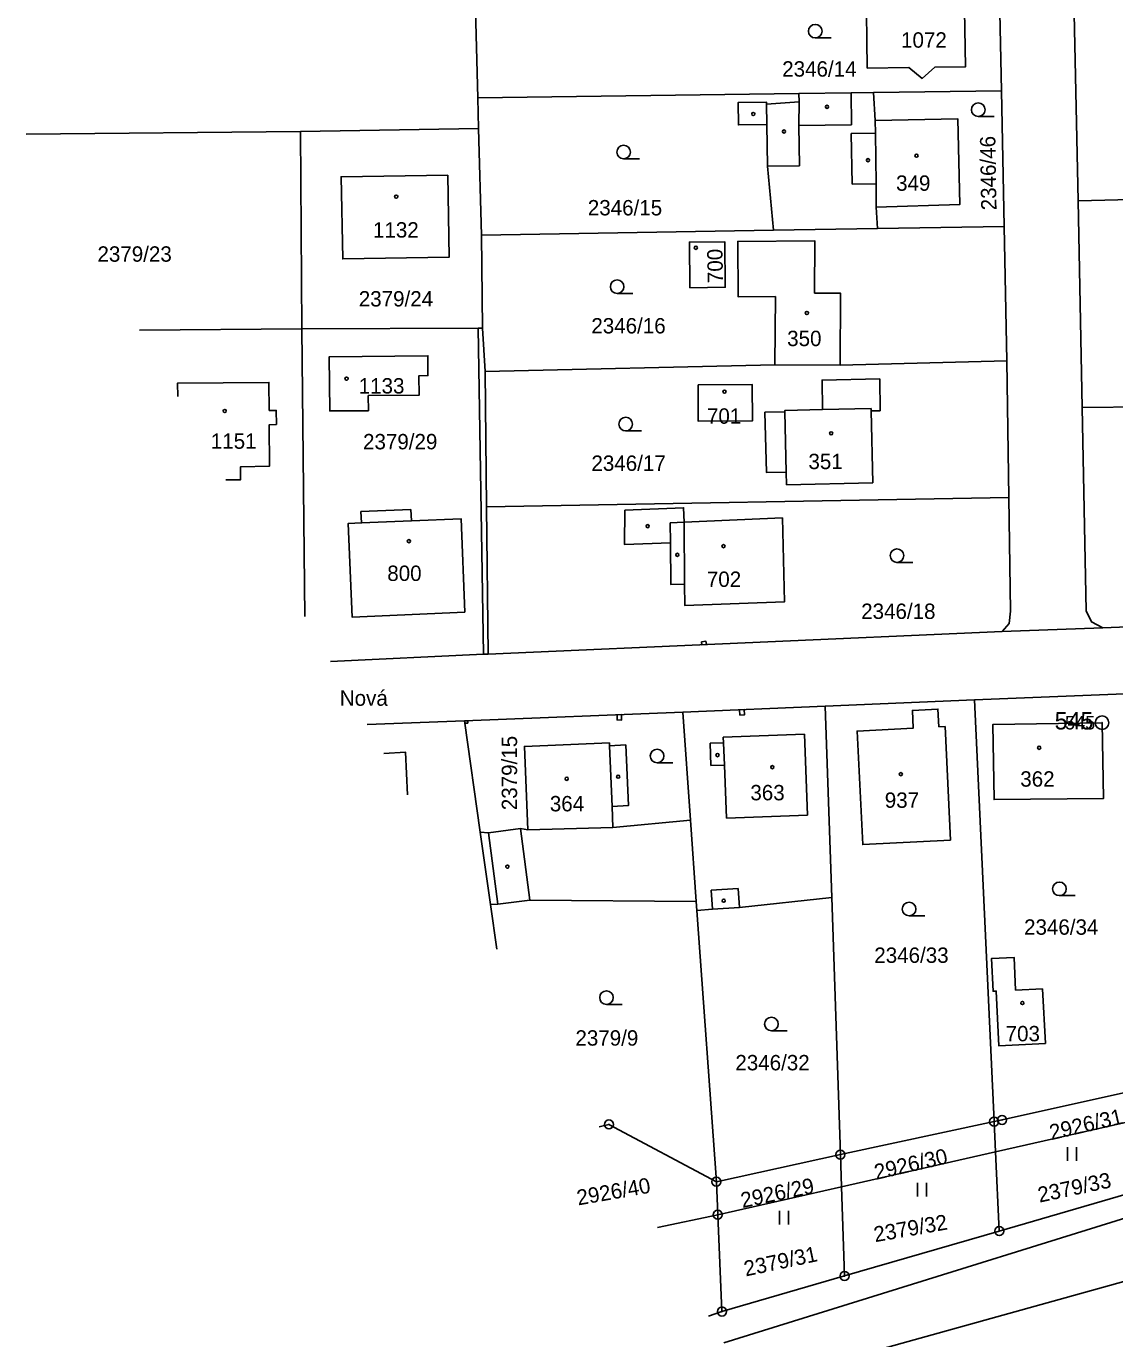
# Model space of a CAD drawing. Extents: x -758836 to -757729, y -1175316 to -1174366.
# Drawn here: x -758829.6 to -758709.3, y -1175013.2 to -1174868.1 of the extents above; entities that cross this region are included whole.
import ezdxf

# ---------------------------------------------------------------- set-up
doc = ezdxf.new("R2010")
doc.units = 0
for name, color, linetype in [('Hranice parcel', 7, 'Continuous'), ('Parcelní čísla', 7, 'Continuous'), ('Pop  PČ popisy', 7, 'Continuous'), ('Vnitřní kresba', 7, 'Continuous'), ('Věcná břemena k části', 7, 'Continuous'), ('Značky bodu BP', 7, 'Continuous'), ('Značky budov', 7, 'Continuous'), ('Značky kultur', 7, 'Continuous')]:
    doc.layers.add(name, color=color, linetype=linetype)

msp = doc.modelspace()

# ---------------------------------------------------------------- linework, layer by layer
at = {"layer": 'Hranice parcel'}
for p, q in [((-758780.07, -1174860.85), (-758779.67, -1174875.98)), ((-758721.79, -1174875.22), (-758722.01, -1174864.11)), ((-758713.75, -1174866.68), (-758713.31, -1174887.37)), ((-758779.67, -1174875.98), (-758744.17, -1174875.51)), ((-758735.94, -1174875.41), (-758721.79, -1174875.22)), ((-758721.79, -1174875.22), (-758721.49, -1174890.19)), ((-758779.67, -1174875.98), (-758779.58, -1174879.39)), ((-758799.28, -1174879.69), (-758779.58, -1174879.39)), ((-758799.14, -1174901.53), (-758799.28, -1174879.69)), ((-758779.58, -1174879.39), (-758779.27, -1174891.16)), ((-758713.31, -1174887.37), (-758668.75, -1174886.35)), ((-758713.31, -1174887.37), (-758712.85, -1174910.23)), ((-758721.49, -1174890.19), (-758735.49, -1174890.42)), ((-758721.19, -1174905.07), (-758721.49, -1174890.19)), ((-758779.27, -1174891.16), (-758746.99, -1174890.62)), ((-758779.27, -1174891.16), (-758779.15, -1174901.44)), ((-758746.99, -1174890.62), (-758735.49, -1174890.42)), ((-758817.08, -1174901.67), (-758799.14, -1174901.53)), ((-758798.81, -1174933.31), (-758799.14, -1174901.53)), ((-758779.15, -1174901.44), (-758778.87, -1174906.24)), ((-758778.87, -1174906.24), (-758746.84, -1174905.5)), ((-758778.87, -1174906.24), (-758778.71, -1174921.21)), ((-758746.84, -1174905.5), (-758739.62, -1174905.55)), ((-758739.62, -1174905.55), (-758721.19, -1174905.07)), ((-758720.97, -1174920.18), (-758721.19, -1174905.07)), ((-758712.85, -1174910.23), (-758694.87, -1174909.97)), ((-758778.71, -1174921.21), (-758720.97, -1174920.18)), ((-758778.71, -1174921.21), (-758778.54, -1174937.47)), ((-758710.56, -1174934.59), (-758670.93, -1174932.75)), ((-758778.54, -1174937.47), (-758721.71, -1174934.99)), ((-758710.56, -1174934.59), (-758721.71, -1174934.99)), ((-758724.75, -1174942.54), (-758741.26, -1174943.23)), ((-758707.25, -1174941.82), (-758724.75, -1174942.54)), ((-758722.59, -1174989.16), (-758724.75, -1174942.54)), ((-758781.15, -1174944.87), (-758757.02, -1174943.88)), ((-758741.26, -1174943.23), (-758757.02, -1174943.88)), ((-758757.02, -1174943.88), (-758756.16, -1174955.85)), ((-758740.54, -1174964.37), (-758741.26, -1174943.23)), ((-758791.91, -1174945.27), (-758781.15, -1174944.87)), ((-758779.41, -1174957.17), (-758781.15, -1174944.87)), ((-758756.16, -1174955.85), (-758755.52, -1174964.83)), ((-758779.41, -1174957.17), (-758778.28, -1174965.17)), ((-758777.58, -1174970.08), (-758778.28, -1174965.17)), ((-758755.52, -1174964.83), (-758755.45, -1174965.82)), ((-758739.58, -1174992.81), (-758740.54, -1174964.37)), ((-758755.45, -1174965.82), (-758753.3, -1174995.8)), ((-758705.17, -1174988.61), (-758722.43, -1174992.51)), ((-758739.58, -1174992.81), (-758722.59, -1174989.16)), ((-758722.43, -1174992.51), (-758722.59, -1174989.16)), ((-758753.3, -1174995.8), (-758739.58, -1174992.81)), ((-758739.46, -1174996.37), (-758739.58, -1174992.81)), ((-758722.43, -1174992.51), (-758739.46, -1174996.37)), ((-758722.03, -1175001.26), (-758722.43, -1174992.51)), ((-758753.3, -1174995.8), (-758753.14, -1174999.46)), ((-758704.83, -1174996.27), (-758722.03, -1175001.26)), ((-758739.46, -1174996.37), (-758753.14, -1174999.46)), ((-758739.13, -1175006.22), (-758739.46, -1174996.37)), ((-758753.14, -1174999.46), (-758759.8, -1175000.88)), ((-758753.14, -1174999.46), (-758752.68, -1175010.15)), ((-758722.03, -1175001.26), (-758739.13, -1175006.22)), ((-758739.13, -1175006.22), (-758752.68, -1175010.15)), ((-758752.68, -1175010.15), (-758754.17, -1175010.65))]:
    msp.add_line(p, q, dxfattribs=at)
for points in [[(-758722.01, -1174864.11), (-758725.89, -1174864.14), (-758725.75, -1174872.55), (-758729.16, -1174872.6), (-758730.53, -1174873.84), (-758732.01, -1174872.64), (-758736.61, -1174872.7), (-758736.74, -1174863.47), (-758728.55, -1174863.36), (-758728.6, -1174860.45), (-758722.09, -1174860.37)], [(-758749.71, -1175018.36), (-758683.75, -1175000), (-758648.73, -1174990.25), (-758595.39, -1174971.76), (-758559.83, -1174954.39), (-758554.18, -1174950.69), (-758542.58, -1174943.09), (-758500.14, -1174908.44), (-758460.25, -1174869.94), (-758457.56, -1174867.46)], [(-758744.17, -1174875.51), (-758744.16, -1174876.44), (-758747.74, -1174876.67), (-758747.75, -1174876.47), (-758750.9, -1174876.51), (-758750.86, -1174878.98), (-758747.71, -1174878.94), (-758747.66, -1174883.53), (-758746.99, -1174890.62)], [(-758735.94, -1174875.41), (-758738.41, -1174875.44), (-758744.17, -1174875.51)], [(-758735.49, -1174890.42), (-758735.62, -1174888.06), (-758726.4, -1174887.78), (-758726.61, -1174878.29), (-758735.74, -1174878.49), (-758735.94, -1174875.41)], [(-758829.59, -1174880), (-758799.28, -1174879.69)], [(-758782.99, -1174884.52), (-758782.84, -1174893.61), (-758794.6, -1174893.79), (-758794.78, -1174884.71), (-758782.99, -1174884.52)], [(-758739.62, -1174905.55), (-758739.57, -1174897.59), (-758742.44, -1174897.57), (-758742.42, -1174891.78), (-758750.93, -1174891.86), (-758750.9, -1174897.97), (-758746.77, -1174897.95), (-758746.84, -1174905.5)], [(-758756.22, -1174896.98), (-758752.32, -1174896.92), (-758752.38, -1174891.89), (-758756.27, -1174891.93), (-758756.22, -1174896.98)], [(-758799.14, -1174901.53), (-758779.65, -1174901.44), (-758779.15, -1174901.44)], [(-758791.78, -1174908.9), (-758791.77, -1174910.58), (-758796.04, -1174910.6), (-758796.09, -1174904.6), (-758785.18, -1174904.49), (-758785.18, -1174906.69), (-758786.18, -1174906.7), (-758786.16, -1174908.87), (-758791.78, -1174908.9)], [(-758812.84, -1174909.01), (-758812.86, -1174907.52), (-758802.77, -1174907.44), (-758802.74, -1174910.55)], [(-758755.31, -1174907.72), (-758755.31, -1174911.73), (-758749.31, -1174911.7), (-758749.33, -1174907.69), (-758755.31, -1174907.72)], [(-758745.54, -1174918.76), (-758736.01, -1174918.54), (-758736.19, -1174910.59), (-758735.2, -1174910.58), (-758735.24, -1174907.05), (-758741.62, -1174907.18), (-758741.57, -1174910.45), (-758745.73, -1174910.55), (-758745.73, -1174910.7), (-758747.93, -1174910.75), (-758747.76, -1174917.4), (-758745.57, -1174917.35), (-758745.54, -1174918.76)], [(-758802.74, -1174910.55), (-758801.95, -1174910.53), (-758801.94, -1174912.09), (-758802.73, -1174912.13), (-758802.69, -1174916.69), (-758805.91, -1174916.79), (-758805.9, -1174918.2), (-758807.53, -1174918.22)], [(-758712.85, -1174910.23), (-758712.4, -1174932.68), (-758711.84, -1174933.91), (-758710.56, -1174934.59)], [(-758721.71, -1174934.99), (-758720.92, -1174934.1), (-758720.79, -1174932.73), (-758720.97, -1174920.18)], [(-758787.06, -1174921.48), (-758792.59, -1174921.72), (-758792.53, -1174922.98), (-758794.02, -1174923.04), (-758793.57, -1174933.38), (-758781.11, -1174932.84), (-758781.52, -1174922.51), (-758787.01, -1174922.74), (-758787.06, -1174921.48)], [(-758745.97, -1174922.41), (-758756.85, -1174922.88), (-758756.92, -1174921.29), (-758763.41, -1174921.57), (-758763.46, -1174925.35), (-758758.38, -1174925.18), (-758758.35, -1174929.77), (-758756.81, -1174929.76), (-758756.79, -1174932.1), (-758745.78, -1174931.71), (-758745.97, -1174922.41)], [(-758778.54, -1174937.47), (-758779.04, -1174937.49), (-758795.94, -1174938.3)], [(-758728.01, -1174945.47), (-758728.7, -1174945.51), (-758728.8, -1174943.55), (-758731.63, -1174943.7), (-758731.53, -1174945.66), (-758737.74, -1174945.99), (-758737.11, -1174958.54), (-758727.42, -1174958.04), (-758728.01, -1174945.47)], [(-758710.66, -1174945.06), (-758722.74, -1174945.27), (-758722.59, -1174953.55), (-758710.51, -1174953.44), (-758710.66, -1174945.06)], [(-758787.44, -1174953.02), (-758787.66, -1174948.32), (-758790.07, -1174948.45)], [(-758756.16, -1174955.85), (-758764.74, -1174956.64), (-758764.83, -1174954.31), (-758763.03, -1174954.23), (-758763.31, -1174947.52), (-758765.11, -1174947.6), (-758765.12, -1174947.3), (-758774.52, -1174947.68), (-758774.14, -1174956.9), (-758774.94, -1174956.76), (-758778.49, -1174957.22), (-758779.41, -1174957.17)], [(-758778.28, -1174965.17), (-758777.47, -1174965.13), (-758773.92, -1174964.68), (-758755.52, -1174964.83)], [(-758755.45, -1174965.82), (-758753.72, -1174965.69), (-758750.73, -1174965.48), (-758740.54, -1174964.37)], [(-758716.93, -1174980.54), (-758717.26, -1174974.49), (-758720.21, -1174974.62), (-758720.38, -1174971), (-758722.88, -1174971.11), (-758722.71, -1174974.74), (-758722.36, -1174974.72), (-758722.08, -1174980.78), (-758716.93, -1174980.54)], [(-758722.59, -1174989.16), (-758721.71, -1174988.97), (-758705.32, -1174985.3)], [(-758766.24, -1174989.74), (-758765.18, -1174989.47), (-758753.3, -1174995.8)], [(-758752.46, -1175013.6), (-758691.55, -1174994.68)]]:
    msp.add_lwpolyline(points, dxfattribs=at)
at = {"layer": 'Vnitřní kresba'}
for p, q in [((-758738.41, -1174875.44), (-758738.36, -1174878.97)), ((-758747.71, -1174878.94), (-758747.74, -1174876.67)), ((-758744.17, -1174879.04), (-758744.16, -1174876.44)), ((-758735.74, -1174878.49), (-758735.72, -1174879.88)), ((-758738.36, -1174878.97), (-758744.17, -1174879.04)), ((-758744.17, -1174879.04), (-758744.12, -1174883.49)), ((-758735.72, -1174879.88), (-758738.4, -1174879.92)), ((-758738.4, -1174879.92), (-758738.28, -1174885.53)), ((-758735.72, -1174879.88), (-758735.65, -1174885.5)), ((-758744.12, -1174883.49), (-758747.66, -1174883.53)), ((-758738.28, -1174885.53), (-758735.65, -1174885.5)), ((-758735.65, -1174885.5), (-758735.62, -1174888.06)), ((-758736.2, -1174910.33), (-758741.57, -1174910.45)), ((-758736.19, -1174910.59), (-758736.2, -1174910.33)), ((-758745.73, -1174910.7), (-758745.57, -1174917.35)), ((-758792.53, -1174922.98), (-758787.01, -1174922.74)), ((-758756.85, -1174922.88), (-758758.39, -1174922.95)), ((-758758.39, -1174922.95), (-758758.38, -1174925.18)), ((-758756.85, -1174922.88), (-758756.81, -1174929.76)), ((-758752.53, -1174946.66), (-758743.57, -1174946.31)), ((-758752.5, -1174947.27), (-758752.53, -1174946.66)), ((-758743.57, -1174946.31), (-758743.22, -1174955.27)), ((-758765.11, -1174947.6), (-758764.83, -1174954.31)), ((-758754, -1174947.33), (-758752.5, -1174947.27)), ((-758753.91, -1174949.8), (-758754, -1174947.33)), ((-758752.5, -1174947.27), (-758752.41, -1174949.74)), ((-758752.41, -1174949.74), (-758753.91, -1174949.8)), ((-758752.18, -1174955.61), (-758752.41, -1174949.74)), ((-758743.22, -1174955.27), (-758752.18, -1174955.61)), ((-758774.94, -1174956.76), (-758773.92, -1174964.68)), ((-758764.74, -1174956.64), (-758774.14, -1174956.9)), ((-758777.47, -1174965.13), (-758778.49, -1174957.22)), ((-758750.87, -1174963.38), (-758753.86, -1174963.58)), ((-758753.86, -1174963.58), (-758753.72, -1174965.69)), ((-758750.73, -1174965.48), (-758750.87, -1174963.38))]:
    msp.add_line(p, q, dxfattribs=at)
at = {"layer": 'Věcná břemena k části'}
for points in [[(-758779.65, -1174901.44), (-758779.04, -1174937.49), (-758778.54, -1174937.47), (-758778.71, -1174921.21), (-758778.87, -1174906.24), (-758779.15, -1174901.44)], [(-758754.9, -1174936.44), (-758754.39, -1174936.42), (-758754.45, -1174936.06), (-758754.94, -1174936.13)], [(-758750.7, -1174944.24), (-758750.2, -1174944.2), (-758750.24, -1174943.6), (-758750.74, -1174943.62)], [(-758781.15, -1174944.87), (-758781.12, -1174945.1), (-758780.78, -1174945.1), (-758780.78, -1174944.85)], [(-758763.77, -1174944.16), (-758764.27, -1174944.18), (-758764.28, -1174944.75), (-758763.78, -1174944.77)]]:
    msp.add_lwpolyline(points, close=True, dxfattribs=at)
at = {"layer": 'Značky bodu BP'}
for centre, radius in [((-758710.66, -1174945.06), 0.75), ((-758710.66, -1174945.06), 0.03), ((-758765.18, -1174989.47), 0.5), ((-758722.59, -1174989.16), 0.5), ((-758721.71, -1174988.97), 0.5), ((-758721.71, -1174988.97), 0.0303), ((-758765.18, -1174989.47), 0.0303), ((-758722.59, -1174989.16), 0.0303), ((-758739.58, -1174992.81), 0.5), ((-758739.58, -1174992.81), 0.0303), ((-758753.3, -1174995.8), 0.5), ((-758753.3, -1174995.8), 0.0303), ((-758753.14, -1174999.46), 0.5), ((-758753.14, -1174999.46), 0.0303), ((-758722.03, -1175001.26), 0.5), ((-758722.03, -1175001.26), 0.0303), ((-758739.13, -1175006.22), 0.5), ((-758739.13, -1175006.22), 0.0303), ((-758752.68, -1175010.15), 0.5), ((-758752.68, -1175010.15), 0.0303)]:
    msp.add_circle(centre, radius, dxfattribs=at)
at = {"layer": 'Značky budov'}
for centre in [(-758741.06, -1174876.98), (-758749.22, -1174877.77), (-758745.82, -1174879.7), (-758736.53, -1174882.87), (-758731.17, -1174882.38), (-758788.69, -1174886.9), (-758755.57, -1174892.56), (-758743.29, -1174899.76), (-758794.18, -1174907.02), (-758752.4, -1174908.46), (-758807.65, -1174910.6), (-758740.61, -1174913.07), (-758760.89, -1174923.33), (-758787.29, -1174924.99), (-758757.61, -1174926.5), (-758752.51, -1174925.54), (-758717.61, -1174947.83), (-758753.17, -1174948.64), (-758747.11, -1174949.98), (-758769.84, -1174951.26), (-758764.15, -1174951.03), (-758732.9, -1174950.75), (-758776.4, -1174960.97), (-758752.49, -1174964.74), (-758719.47, -1174976.05)]:
    msp.add_circle(centre, 0.175, dxfattribs=at)
at = {"layer": 'Značky kultur'}
for p, q in [((-758742.37, -1174869.36), (-758740.62, -1174869.36)), ((-758724.35, -1174878.05), (-758722.6, -1174878.05)), ((-758763.55, -1174882.73), (-758761.8, -1174882.73)), ((-758764.27, -1174897.61), (-758762.52, -1174897.61)), ((-758763.32, -1174912.8), (-758761.57, -1174912.8)), ((-758733.33, -1174927.34), (-758731.58, -1174927.34)), ((-758759.85, -1174949.49), (-758758.1, -1174949.49)), ((-758715.37, -1174964.18), (-758713.62, -1174964.18)), ((-758731.99, -1174966.41), (-758730.24, -1174966.41)), ((-758765.45, -1174976.2), (-758763.7, -1174976.2)), ((-758747.21, -1174979.12), (-758745.46, -1174979.12)), ((-758714.47, -1174993.49), (-758714.47, -1174991.99)), ((-758713.47, -1174993.49), (-758713.47, -1174991.99)), ((-758731.06, -1174997.43), (-758731.06, -1174995.93)), ((-758730.06, -1174997.43), (-758730.06, -1174995.93)), ((-758746.31, -1175000.53), (-758746.31, -1174999.03)), ((-758745.31, -1175000.53), (-758745.31, -1174999.03))]:
    msp.add_line(p, q, dxfattribs=at)
for centre in [(-758742.37, -1174868.61), (-758724.35, -1174877.3), (-758763.55, -1174881.98), (-758764.27, -1174896.86), (-758763.32, -1174912.05), (-758733.33, -1174926.59), (-758759.85, -1174948.74), (-758715.37, -1174963.43), (-758731.99, -1174965.66), (-758765.45, -1174975.45), (-758747.21, -1174978.37)]:
    msp.add_circle(centre, 0.75, dxfattribs=at)

# ---------------------------------------------------------------- texts
at = {"layer": 'Parcelní čísla'}
for s, p in [('1072', (-758732.88, -1174870.44)), ('2346/14', (-758746.02, -1174873.64)), ('349', (-758733.43, -1174886.26)), ('2346/15', (-758767.51, -1174888.98)), ('1132', (-758791.26, -1174891.43)), ('2379/23', (-758821.72, -1174894.1)), ('2379/24', (-758792.83, -1174899.05)), ('2346/16', (-758767.12, -1174902.03)), ('350', (-758745.47, -1174903.43)), ('1133', (-758792.84, -1174908.67)), ('701', (-758754.34, -1174912.01)), ('1151', (-758809.19, -1174914.78)), ('2379/29', (-758792.36, -1174914.84)), ('2346/17', (-758767.11, -1174917.22)), ('351', (-758743.12, -1174917.03)), ('800', (-758789.68, -1174929.39)), ('702', (-758754.35, -1174930.05)), ('2346/18', (-758737.29, -1174933.59)), ('362', (-758719.7, -1174952.13)), ('363', (-758749.54, -1174953.64)), ('937', (-758734.68, -1174954.47)), ('364', (-758771.71, -1174954.86)), ('2346/34', (-758719.28, -1174968.5)), ('2346/33', (-758735.84, -1174971.61)), ('703', (-758721.32, -1174980.28)), ('2379/9', (-758768.88, -1174980.76)), ('2346/32', (-758751.2, -1174983.49))]:
    msp.add_text(s, height=1.7, dxfattribs=at).set_placement(p)
for s, rotation, p in [('2346/46', 91, (-758722.32, -1174888.4)), ('700', 91, (-758752.56, -1174896.45)), ('2379/15', 90, (-758775.33, -1174954.73)), ('2926/31', 13, (-758716.26, -1174991.21)), ('2926/30', 13, (-758735.62, -1174995.6)), ('2379/33', 12, (-758717.57, -1174998.12)), ('2926/40', 10, (-758768.57, -1174998.43)), ('2926/29', 12, (-758750.41, -1174998.72)), ('2379/32', 10, (-758735.74, -1175002.49)), ('2379/31', 12, (-758750.05, -1175006.28))]:
    msp.add_text(s, height=1.7, rotation=rotation, dxfattribs=at).set_placement(p)
at = {"layer": 'Pop  PČ popisy'}
msp.add_text('Nová', height=1.7, dxfattribs=at).set_placement((-758794.93, -1174943.19))
at = {"layer": 'Značky bodu BP'}
for height, p in [(1.919, (-758715.9, -1174945.81)), (1.5, (-758714.76, -1174945.81))]:
    msp.add_text('545', height=height, dxfattribs=at).set_placement(p)

doc.saveas('drawing.dxf')
